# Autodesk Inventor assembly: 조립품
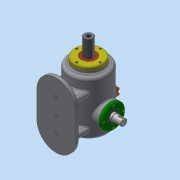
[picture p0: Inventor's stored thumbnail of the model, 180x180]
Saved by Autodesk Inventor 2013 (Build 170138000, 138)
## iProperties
Created: 2017-01
Part Number: 조립품
Document SubType Name: Assembly
Designer: dgall
Author: dgall
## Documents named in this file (16)
- C:\Users\dgall\Desktop\370107V1014\답안조립품.iam
- C:\Users\dgall\Desktop\370107V1014\본체.ipt
- C:\Users\dgall\Desktop\370107V1014\플레이트.ipt
- C:\Users\dgall\Desktop\370107V1014\베어링 6205.ipt
- 베어링 6205.ipt
- C:\Users\dgall\Desktop\370107V1014\축 커버-1.ipt
- C:\Users\dgall\Desktop\370107V1014\축 커버-2.ipt
- C:\Users\dgall\Desktop\370107V1014\오일실.ipt
- 오일실.ipt
- C:\Users\dgall\Desktop\370107V1014\슬라이드 커버.ipt
- C:\Users\dgall\Desktop\370107V1014\부시.ipt
- C:\Users\dgall\Desktop\370107V1014\편심축.ipt
- C:\Users\dgall\Desktop\370107V1014\슬라이드.ipt
- C:\Users\dgall\Desktop\370107V1014\볼트 M4x0.7.ipt
- C:\Users\dgall\Desktop\370107V1014\상부 캡.ipt
- C:\Users\dgall\Desktop\370107V1014\가변스프링.ipt
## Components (14 placed, 3 different names)
1. 플레이트:1
2. M4x0.7:1
3. M4x0.7:2
4. M4x0.7:3
5. M4x0.7:4
6. M4x0.7:5
7. M4x0.7:6
8. M4x0.7:7
9. M4x0.7:8
10. M4x0.7:9
11. M4x0.7:10
12. M4x0.7:11
13. M4x0.7:12
14. 가변스프링:1
